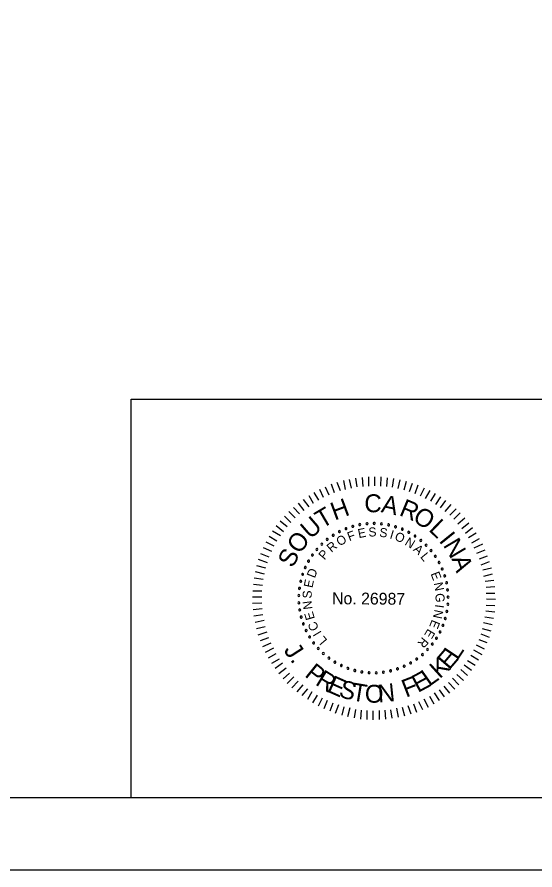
# Model space of a CAD drawing. Extents: x 96 to 240, y 601 to 689.
# Drawn here: x 183.22 to 197.53, y 601 to 624.55 of the extents above; entities that cross this region are included whole.
import ezdxf

# ---------------------------------------------------------------- set-up
doc = ezdxf.new("R2010")
doc.units = 0
for name, color, linetype in [('BR_BORDER LINES', 7, 'Continuous'), ('BR_TEXT', 7, 'Continuous'), ('Level 31', 7, 'Continuous')]:
    doc.layers.add(name, color=color, linetype=linetype)

msp = doc.modelspace()

# ---------------------------------------------------------------- linework, layer by layer
at = {"layer": 'BR_BORDER LINES'}
for p, q in [((186.375, 614.004), (207.836, 614.004)), ((186.375, 603.004), (186.375, 614.004)), ((103.173, 603.003), (237.837, 603.003))]:
    msp.add_line(p, q, dxfattribs=at)
at = {"layer": 'BR_TEXT'}
for p, q in [((192.299, 611.507), (192.246, 611.751)), ((192.464, 611.546), (192.407, 611.784)), ((192.622, 611.576), (192.586, 611.82)), ((192.78, 611.592), (192.765, 611.836)), ((192.938, 611.601), (192.94, 611.858)), ((193.106, 611.61), (193.108, 611.857)), ((193.274, 611.598), (193.283, 611.856)), ((193.435, 611.587), (193.455, 611.83)), ((193.59, 611.568), (193.633, 611.811)), ((193.751, 611.536), (193.808, 611.772)), ((193.915, 611.493), (193.979, 611.736)), ((191.693, 611.282), (191.588, 611.506)), ((191.841, 611.349), (191.747, 611.573)), ((191.996, 611.416), (191.912, 611.651)), ((192.154, 611.467), (192.067, 611.697)), ((194.063, 611.451), (194.15, 611.68)), ((194.22, 611.398), (194.308, 611.631)), ((194.364, 611.328), (194.475, 611.55)), ((194.507, 611.258), (194.633, 611.481)), ((191.413, 611.116), (191.292, 611.333)), ((191.555, 611.211), (191.433, 611.428)), ((194.658, 611.185), (194.787, 611.4)), ((194.791, 611.088), (194.927, 611.303)), ((191.023, 610.831), (190.856, 611.01)), ((191.154, 610.929), (190.995, 611.13)), ((191.289, 611.031), (191.133, 611.235)), ((194.924, 611.001), (195.07, 611.202)), ((195.054, 610.897), (195.216, 611.095)), ((190.905, 610.722), (190.728, 610.898)), ((195.18, 610.796), (195.353, 610.973)), ((195.292, 610.686), (195.465, 610.859)), ((190.687, 610.473), (190.489, 610.629)), ((190.788, 610.599), (190.614, 610.769)), ((195.404, 610.561), (195.595, 610.728)), ((195.513, 610.433), (195.7, 610.586)), ((190.496, 610.224), (190.281, 610.356)), ((190.583, 610.34), (190.385, 610.5)), ((195.608, 610.298), (195.805, 610.455)), ((195.696, 610.181), (195.907, 610.31)), ((190.399, 610.077), (190.184, 610.206)), ((195.784, 610.033), (195.998, 610.158)), ((190.259, 609.793), (190.03, 609.895)), ((190.329, 609.94), (190.103, 610.052)), ((195.855, 609.895), (196.086, 610.003)), ((195.926, 609.747), (196.154, 609.844)), ((190.189, 609.639), (189.957, 609.727)), ((195.994, 609.592), (196.221, 609.675)), ((190.091, 609.335), (189.847, 609.395)), ((190.14, 609.479), (189.894, 609.57)), ((196.047, 609.43), (196.278, 609.517)), ((190.062, 609.167), (189.812, 609.231)), ((196.087, 609.285), (196.328, 609.342)), ((196.12, 609.117), (196.361, 609.177)), ((190.019, 609.023), (189.776, 609.056)), ((196.153, 608.972), (196.39, 609.001)), ((189.989, 608.701), (189.732, 608.703)), ((190.001, 608.858), (189.754, 608.888)), ((196.179, 608.807), (196.423, 608.833)), ((189.981, 608.536), (189.73, 608.538)), ((196.185, 608.649), (196.425, 608.647)), ((196.194, 608.485), (196.438, 608.483)), ((189.986, 608.364), (189.729, 608.359)), ((189.996, 608.21), (189.748, 608.181)), ((196.182, 608.313), (196.422, 608.304)), ((190.011, 608.045), (189.767, 608.009)), ((196.145, 607.994), (196.382, 607.954)), ((196.174, 608.159), (196.418, 608.126)), ((190.051, 607.887), (189.8, 607.834)), ((190.077, 607.718), (189.833, 607.662)), ((196.11, 607.837), (196.349, 607.78)), ((190.124, 607.57), (189.876, 607.486)), ((196.031, 607.521), (196.261, 607.434)), ((196.074, 607.669), (196.314, 607.608)), ((190.171, 607.415), (189.937, 607.331)), ((190.238, 607.267), (190.007, 607.159)), ((195.975, 607.367), (196.201, 607.28)), ((190.306, 607.122), (190.078, 607.004)), ((195.832, 607.077), (196.061, 606.955)), ((195.905, 607.22), (196.131, 607.109)), ((190.373, 606.974), (190.156, 606.849)), ((190.468, 606.826), (190.251, 606.701)), ((195.668, 606.783), (195.877, 606.654)), ((195.759, 606.93), (195.971, 606.801)), ((190.553, 606.708), (190.353, 606.562)), ((190.655, 606.574), (190.454, 606.417)), ((195.578, 606.667), (195.773, 606.518)), ((190.753, 606.439), (190.577, 606.276)), ((190.869, 606.335), (190.689, 606.155)), ((195.256, 606.299), (195.426, 606.115)), ((195.37, 606.401), (195.557, 606.234)), ((195.481, 606.534), (195.665, 606.374)), ((190.985, 606.214), (190.815, 606.03)), ((191.114, 606.11), (190.952, 605.922)), ((195.014, 606.078), (195.173, 605.888)), ((195.142, 606.18), (195.312, 605.993)), ((191.248, 606.006), (191.088, 605.815)), ((191.37, 605.919), (191.245, 605.711)), ((191.51, 605.829), (191.385, 605.613)), ((194.748, 605.891), (194.88, 605.681)), ((194.883, 605.976), (195.025, 605.782)), ((191.647, 605.749), (191.539, 605.526)), ((191.794, 605.679), (191.696, 605.456)), ((191.948, 605.609), (191.86, 605.383)), ((194.317, 605.658), (194.425, 605.434)), ((194.462, 605.725), (194.583, 605.501)), ((194.613, 605.803), (194.739, 605.586)), ((192.105, 605.559), (192.014, 605.327)), ((192.249, 605.51), (192.192, 605.274)), ((192.414, 605.481), (192.353, 605.235)), ((192.571, 605.435), (192.532, 605.202)), ((192.729, 605.417), (192.71, 605.17)), ((192.887, 605.405), (192.885, 605.158)), ((193.055, 605.394), (193.053, 605.15)), ((193.223, 605.403), (193.228, 605.155)), ((193.384, 605.412), (193.4, 605.164)), ((193.539, 605.427), (193.578, 605.194)), ((193.701, 605.471), (193.754, 605.223)), ((193.866, 605.497), (193.926, 605.259)), ((194.014, 605.544), (194.098, 605.309)), ((194.172, 605.59), (194.256, 605.363))]:
    msp.add_line(p, q, dxfattribs=at)
for centre, start, end in [((192.692, 610.536), 10.6038, 190.6038), ((192.692, 610.536), 190.6038, 10.6038), ((192.89, 610.563), 5.0653, 185.0653), ((192.89, 610.563), 185.0653, 5.0653), ((193.089, 610.57), 359.5268, 179.5268), ((193.089, 610.57), 179.5268, 359.5268), ((193.288, 610.558), 353.9884, 173.9884), ((193.288, 610.558), 173.9884, 353.9884), ((193.485, 610.528), 348.4499, 168.4499), ((192.128, 610.344), 27.2191, 207.2191), ((192.128, 610.344), 207.2191, 27.2191), ((192.31, 610.426), 21.6807, 201.6807), ((192.31, 610.426), 201.6807, 21.6807), ((192.498, 610.49), 16.1422, 196.1422), ((192.498, 610.49), 196.1422, 16.1422), ((193.485, 610.528), 168.4499, 348.4499), ((193.678, 610.478), 162.9114, 342.9114), ((193.678, 610.478), 342.9114, 162.9114), ((193.865, 610.41), 157.373, 337.373), ((193.865, 610.41), 337.373, 157.373), ((194.045, 610.324), 151.8345, 331.8345), ((194.045, 610.324), 331.8345, 151.8345), ((191.793, 610.129), 38.2961, 218.2961), ((191.793, 610.129), 218.2961, 38.2961), ((191.955, 610.244), 32.7576, 212.7576), ((191.955, 610.244), 212.7576, 32.7576), ((194.216, 610.221), 146.2961, 326.2961), ((194.216, 610.221), 326.2961, 146.2961), ((194.376, 610.102), 140.7576, 320.7576), ((194.376, 610.102), 320.7576, 140.7576), ((191.505, 609.854), 49.373, 229.373), ((191.505, 609.854), 229.373, 49.373), ((191.642, 609.998), 43.8345, 223.8345), ((191.642, 609.998), 223.8345, 43.8345), ((194.524, 609.969), 135.2191, 315.2191), ((194.524, 609.969), 315.2191, 135.2191), ((194.658, 609.821), 129.6807, 309.6807), ((194.658, 609.821), 309.6807, 129.6807), ((191.382, 609.697), 54.9114, 234.9114), ((191.382, 609.697), 234.9114, 54.9114), ((194.777, 609.662), 124.1422, 304.1422), ((194.777, 609.662), 304.1422, 124.1422), ((191.185, 609.351), 65.9884, 245.9884), ((191.185, 609.351), 245.9884, 65.9884), ((191.275, 609.528), 60.4499, 240.4499), ((191.275, 609.528), 240.4499, 60.4499), ((194.881, 609.491), 118.6038, 298.6038), ((194.881, 609.491), 298.6038, 118.6038), ((191.113, 609.165), 71.5268, 251.5268), ((191.113, 609.165), 251.5268, 71.5268), ((194.967, 609.312), 113.0653, 293.0653), ((194.967, 609.312), 293.0653, 113.0653), ((195.036, 609.125), 107.5268, 287.5268), ((195.036, 609.125), 287.5268, 107.5268), ((191.058, 608.973), 77.0653, 257.0653), ((191.058, 608.973), 257.0653, 77.0653), ((195.087, 608.932), 101.9884, 281.9884), ((195.087, 608.932), 281.9884, 101.9884), ((191.023, 608.777), 82.6038, 262.6038), ((191.023, 608.777), 262.6038, 82.6038), ((195.118, 608.735), 96.4499, 276.4499), ((195.118, 608.735), 276.4499, 96.4499), ((191.006, 608.578), 88.1422, 268.1422), ((191.006, 608.578), 268.1422, 88.1422), ((195.131, 608.536), 90.9114, 270.9114), ((195.131, 608.536), 270.9114, 90.9114), ((191.009, 608.379), 93.6807, 273.6807), ((191.031, 608.181), 99.2191, 279.2191), ((191.009, 608.379), 273.6807, 93.6807), ((191.031, 608.181), 279.2191, 99.2191), ((195.124, 608.337), 85.373, 265.373), ((195.124, 608.337), 265.373, 85.373), ((191.072, 607.986), 104.7576, 284.7576), ((191.072, 607.986), 284.7576, 104.7576), ((195.053, 607.945), 74.2961, 254.2961), ((195.053, 607.945), 254.2961, 74.2961), ((195.098, 608.139), 79.8345, 259.8345), ((195.098, 608.139), 259.8345, 79.8345), ((191.132, 607.796), 110.2961, 290.2961), ((191.132, 607.796), 290.2961, 110.2961), ((194.989, 607.756), 68.7576, 248.7576), ((194.989, 607.756), 248.7576, 68.7576), ((191.209, 607.612), 115.8345, 295.8345), ((191.209, 607.612), 295.8345, 115.8345), ((194.908, 607.574), 63.2191, 243.2191), ((194.908, 607.574), 243.2191, 63.2191), ((191.305, 607.437), 121.373, 301.373), ((191.305, 607.437), 301.373, 121.373), ((191.416, 607.272), 126.9114, 306.9114), ((191.416, 607.272), 306.9114, 126.9114), ((194.694, 607.238), 52.1422, 232.1422), ((194.694, 607.238), 232.1422, 52.1422), ((194.809, 607.401), 57.6807, 237.6807), ((194.809, 607.401), 237.6807, 57.6807), ((191.543, 607.118), 132.4499, 312.4499), ((191.543, 607.118), 312.4499, 132.4499), ((191.684, 606.977), 317.9884, 137.9884), ((194.564, 607.087), 46.6038, 226.6038), ((194.564, 607.087), 226.6038, 46.6038), ((191.684, 606.977), 137.9884, 317.9884), ((191.838, 606.851), 143.5268, 323.5268), ((191.838, 606.851), 323.5268, 143.5268), ((194.263, 606.826), 35.5268, 215.5268), ((194.263, 606.826), 215.5268, 35.5268), ((194.42, 606.949), 41.0653, 221.0653), ((194.42, 606.949), 221.0653, 41.0653), ((192.004, 606.74), 149.0653, 329.0653), ((192.004, 606.74), 329.0653, 149.0653), ((192.18, 606.646), 154.6038, 334.6038), ((192.18, 606.646), 334.6038, 154.6038), ((192.363, 606.569), 160.1422, 340.1422), ((192.363, 606.569), 340.1422, 160.1422), ((192.554, 606.51), 345.6807, 165.6807), ((193.733, 606.555), 18.9114, 198.9114), ((193.733, 606.555), 198.9114, 18.9114), ((193.918, 606.628), 24.4499, 204.4499), ((193.918, 606.628), 204.4499, 24.4499), ((194.095, 606.719), 29.9884, 209.9884), ((194.095, 606.719), 209.9884, 29.9884), ((192.554, 606.51), 165.6807, 345.6807), ((192.749, 606.469), 351.2191, 171.2191), ((192.749, 606.469), 171.2191, 351.2191), ((192.947, 606.448), 356.7576, 176.7576), ((192.947, 606.448), 176.7576, 356.7576), ((193.146, 606.446), 2.2961, 182.2961), ((193.146, 606.446), 182.2961, 2.2961), ((193.345, 606.463), 7.8345, 187.8345), ((193.345, 606.463), 187.8345, 7.8345), ((193.541, 606.5), 13.373, 193.373), ((193.541, 606.5), 193.373, 13.373)]:
    msp.add_arc(centre, 0.028, start, end, dxfattribs=at)
at = {"layer": 'Level 31'}
msp.add_lwpolyline([(95.84, 601.004), (239.84, 601.004), (239.84, 689.004), (95.84, 689.004)], close=True, dxfattribs=at)

# ---------------------------------------------------------------- texts
at = {"layer": 'BR_TEXT'}
for s, height, rotation, p in [('H', 0.496, 20.3637, (191.997, 610.647)), ('C', 0.496, 359.5482, (192.815, 610.88)), ('A', 0.496, 348.1981, (193.261, 610.884)), ('T', 0.496, 30.4992, (191.646, 610.417)), ('R', 0.496, 337.4344, (193.754, 610.804)), ('U', 0.496, 40.8022, (191.321, 610.118)), ('O', 0.496, 326.5869, (194.123, 610.657)), ('L', 0.496, 315.9488, (194.573, 610.386)), ('O', 0.496, 52.0267, (191.023, 609.702)), ('F', 0.249, 20.6127, (192.402, 610.076)), ('E', 0.249, 11.4103, (192.663, 610.162)), ('S', 0.249, 2.208, (192.934, 610.206)), ('S', 0.249, 352.6608, (193.22, 610.206)), ('I', 0.249, 343.1136, (193.5, 610.157)), ('O', 0.249, 338.4392, (193.634, 610.117)), ('I', 0.496, 308.6613, (194.859, 610.089)), ('O', 0.249, 30.8477, (192.133, 609.932)), ('N', 0.249, 328.2042, (193.913, 609.991)), ('N', 0.496, 300.7037, (194.981, 609.971)), ('S', 0.496, 63.2511, (190.842, 609.32)), ('P', 0.249, 49.9421, (191.716, 609.546)), ('R', 0.249, 40.3949, (191.908, 609.756)), ('A', 0.249, 318.657, (194.149, 609.831)), ('L', 0.249, 309.4546, (194.348, 609.642)), ('A', 0.496, 289.4792, (195.218, 609.599)), ('D', 0.249, 69.0364, (191.448, 609.045)), ('E', 0.249, 291.049, (194.643, 609.181)), ('E', 0.249, 78.2388, (191.382, 608.778)), ('N', 0.249, 281.8466, (194.732, 608.921)), ('S', 0.249, 87.786, (191.359, 608.494)), ('No. 26987', 0.327, 359.5268, (191.924, 608.34)), ('N', 0.249, 97.3332, (191.384, 608.21)), ('G', 0.249, 272.2995, (194.779, 608.639)), ('I', 0.249, 262.4084, (194.778, 608.344)), ('E', 0.249, 106.5355, (191.452, 607.944)), ('N', 0.249, 257.7339, (194.759, 608.206)), ('C', 0.249, 116.4266, (191.571, 607.674)), ('E', 0.249, 248.1867, (194.687, 607.93)), ('I', 0.249, 121.1011, (191.644, 607.554)), ('L', 0.249, 129.9595, (191.806, 607.345)), ('E', 0.249, 238.9844, (194.575, 607.679)), ('R', 0.249, 229.782, (194.425, 607.449)), ('J', 0.494, 302.9559, (190.575, 607.071)), ('E', 0.494, 49.3639, (195.159, 606.504)), ('L', 0.494, 56.4247, (195.389, 606.775)), ('.', 0.494, 309.3974, (190.751, 606.8)), ('K', 0.494, 42.3031, (194.897, 606.263)), ('P', 0.494, 321.1035, (191.145, 606.363)), ('R', 0.494, 328.5359, (191.438, 606.13)), ('E', 0.494, 335.9684, (191.758, 605.938)), ('F', 0.494, 21.1206, (193.966, 605.758)), ('E', 0.494, 28.1814, (194.296, 605.887)), ('L', 0.494, 35.2422, (194.608, 606.057)), ('S', 0.494, 343.0292, (192.084, 605.795)), ('T', 0.494, 350.4617, (192.442, 605.689)), ('O', 0.494, 358.1419, (192.824, 605.629)), ('N', 0.494, 5.8221, (193.21, 605.621))]:
    msp.add_text(s, height=height, rotation=rotation, dxfattribs=at).set_placement(p)

doc.saveas('drawing.dxf')
